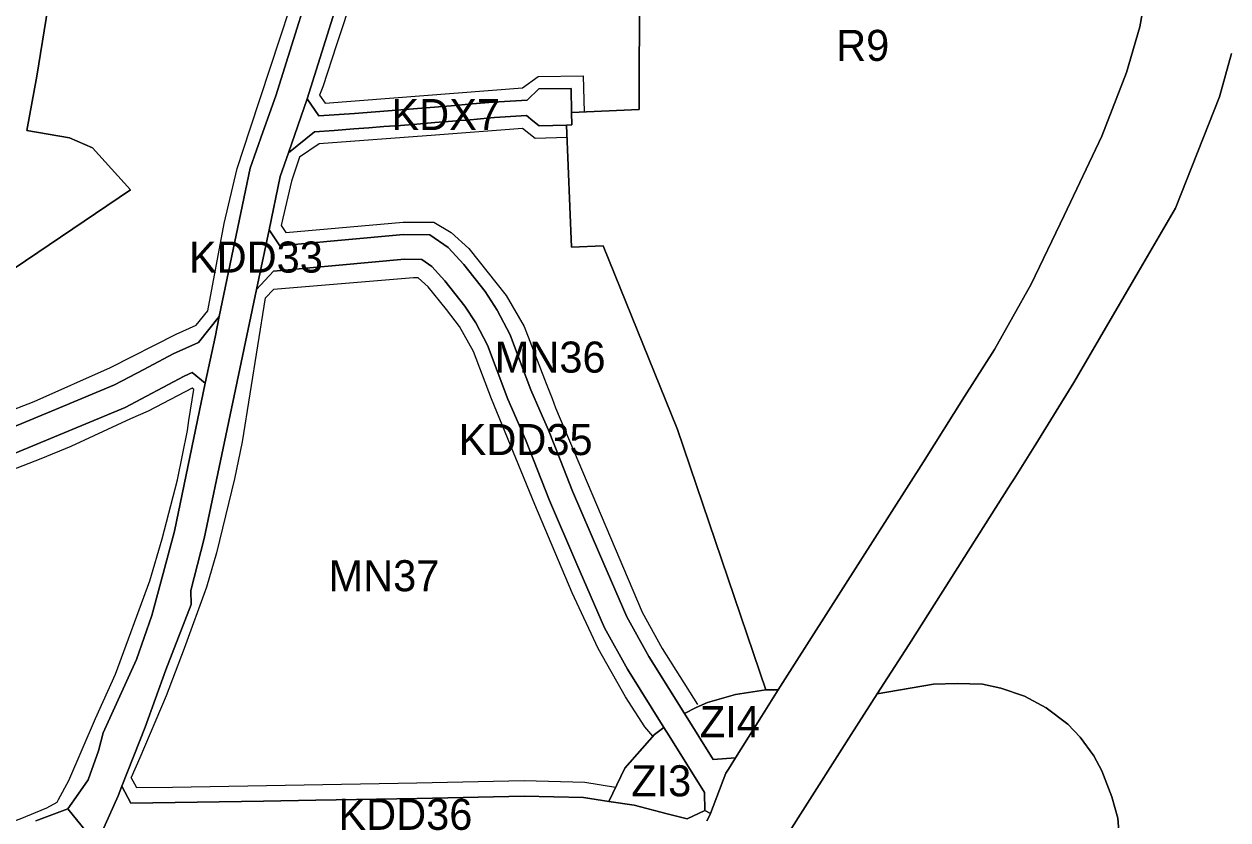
# Model space of a CAD drawing. Extents: x 7428841 to 7433518, y 5545054 to 5546840.
# Drawn here: x 7431568.9 to 7431956.4, y 5546005.4 to 5546261.6 of the extents above; entities that cross this region are included whole.
import ezdxf

# ---------------------------------------------------------------- set-up
doc = ezdxf.new("R2010")
doc.units = 0
for name, color, linetype in [('linie_rozgraniczajace', 7, 'Continuous'), ('linie_zabudowy_nieprzekraczalne', 7, 'Continuous'), ('oznaczenia_przeznaczen', 7, 'Continuous')]:
    doc.layers.add(name, color=color, linetype=linetype)

msp = doc.modelspace()

# ---------------------------------------------------------------- linework, layer by layer
at = {"layer": 'linie_rozgraniczajace'}
for points in [[(7431546.61, 5546302.36), (7431581.61, 5546322.94), (7431625.25, 5546344.76), (7431645.08, 5546352.52), (7431648.04, 5546353.82), (7431649.59, 5546329.66), (7431629.92, 5546324.21), (7431628.71, 5546297.68), (7431577.2, 5546270.87), (7431573.01, 5546244.86), (7431569.77, 5546227.41), (7431583.51, 5546224.99), (7431590.89, 5546221.81), (7431603.1, 5546208.27), (7431498.28, 5546137.46)], [(7431498.28, 5546137.46), (7431603.1, 5546208.27), (7431590.89, 5546221.81), (7431583.51, 5546224.99), (7431569.77, 5546227.41), (7431573.01, 5546244.86), (7431577.2, 5546270.87), (7431628.71, 5546297.68), (7431648.22, 5546299.54), (7431648.57, 5546306.31), (7431670.95, 5546315.15), (7431674.31, 5546316.64), (7431665.23, 5546287.62), (7431649.87, 5546238.51), (7431645.77, 5546226.85), (7431641.66, 5546215.2), (7431631.7, 5546167.48), (7431625.03, 5546159.14), (7431616.9, 5546155.4), (7431607.47, 5546150.42), (7431598.03, 5546145.44), (7431580.23, 5546138.04), (7431562.44, 5546130.63)], [(7431674.71, 5546284.42), (7431660.04, 5546237.52), (7431654.01, 5546220.15), (7431651.31, 5546212.5), (7431647.72, 5546195.4), (7431643.68, 5546176.2), (7431633.35, 5546127.08), (7431626.81, 5546095.96), (7431622.56, 5546079.22), (7431622.65, 5546074.73), (7431614.52, 5546053.71), (7431611.2, 5546044.48), (7431607.88, 5546035.26), (7431600.36, 5546016.23), (7431599.12, 5546013.1), (7431592.16, 5545997.56), (7431583, 5546008.93), (7431586.25, 5546013.62), (7431589.49, 5546018.31), (7431592.79, 5546027.59), (7431594.34, 5546033.44), (7431599.71, 5546045.24), (7431605.09, 5546057.05), (7431610.01, 5546071.18), (7431613.63, 5546084.76), (7431617.26, 5546098.34), (7431627.21, 5546146.01), (7431630.34, 5546160.78), (7431631.7, 5546167.48), (7431641.66, 5546215.2), (7431645.77, 5546226.85), (7431649.87, 5546238.51), (7431665.23, 5546287.62)], [(7431930.86, 5546276.41), (7431927.98, 5546260.72), (7431923.73, 5546245.99), (7431915.83, 5546225.51), (7431903.7, 5546199.96), (7431893.06, 5546177.91), (7431881.23, 5546156.88), (7431871.62, 5546141.76), (7431858.41, 5546120.71), (7431816.89, 5546055.56), (7431811.64, 5546047.22), (7431807.66, 5546047.21), (7431779.21, 5546131.09), (7431755.31, 5546190.25), (7431745.11, 5546189.84), (7431743.51, 5546229.12), (7431745.21, 5546229.17), (7431745.12, 5546233.11), (7431766.85, 5546234.13), (7431766.93, 5546274.9)], [(7431788.64, 5546005.06), (7431789.53, 5546006.64), (7431789.84, 5546007.46), (7431794.74, 5546020.38), (7431795.6, 5546021.73), (7431797.85, 5546025.31), (7431806.24, 5546038.64), (7431811.64, 5546047.22), (7431816.89, 5546055.56), (7431858.41, 5546120.71), (7431871.62, 5546141.76), (7431881.23, 5546156.88), (7431893.06, 5546177.91), (7431903.7, 5546199.96), (7431915.83, 5546225.51), (7431923.73, 5546245.99), (7431927.98, 5546260.72), (7431930.86, 5546276.41)], [(7431957.51, 5546252.19), (7431953.65, 5546238.16), (7431939.54, 5546202.36), (7431927.53, 5546181.78), (7431915.06, 5546160.4), (7431906.77, 5546146.18), (7431894.59, 5546126.38), (7431887.56, 5546115.23), (7431886.51, 5546113.57), (7431853.68, 5546061.76), (7431843.52, 5546046.02), (7431835.06, 5546032.92), (7431818, 5546006.01), (7431813.6, 5545999.06)], [(7431921.47, 5545998.98), (7431920.92, 5546005.95), (7431919.06, 5546012.76), (7431915.83, 5546021.16), (7431913.16, 5546026), (7431908.86, 5546032.02), (7431904.8, 5546036.2), (7431897.88, 5546041.48), (7431890.85, 5546045.25), (7431883.31, 5546047.84), (7431877.35, 5546049.04), (7431869.18, 5546049.29), (7431861.6, 5546049.13), (7431843.52, 5546046.02), (7431853.68, 5546061.76), (7431886.51, 5546113.57), (7431887.56, 5546115.23), (7431894.59, 5546126.38), (7431906.77, 5546146.18), (7431915.06, 5546160.4), (7431927.53, 5546181.78), (7431939.54, 5546202.36), (7431953.65, 5546238.16), (7431957.51, 5546252.19)], [(7431562.44, 5546130.63), (7431580.23, 5546138.04), (7431598.03, 5546145.44), (7431607.47, 5546150.42), (7431616.9, 5546155.4), (7431625.03, 5546159.14), (7431631.7, 5546167.48), (7431630.34, 5546160.78), (7431627.21, 5546146.01), (7431623.03, 5546149.42), (7431620.44, 5546148.22), (7431601.44, 5546138.2), (7431565.99, 5546123.45)], [(7431565.99, 5546123.45), (7431601.44, 5546138.2), (7431620.44, 5546148.22), (7431623.03, 5546149.42), (7431627.21, 5546146.01), (7431617.26, 5546098.34), (7431613.63, 5546084.76), (7431610.01, 5546071.18), (7431605.09, 5546057.05), (7431599.71, 5546045.24), (7431594.34, 5546033.44), (7431592.79, 5546027.59), (7431589.49, 5546018.31), (7431586.25, 5546013.62), (7431583, 5546008.93), (7431572.65, 5546005.07)], [(7431813.6, 5545999.06), (7431818, 5546006.01), (7431835.06, 5546032.92), (7431843.52, 5546046.02), (7431861.6, 5546049.13), (7431869.18, 5546049.29), (7431877.35, 5546049.04), (7431883.31, 5546047.84), (7431890.85, 5546045.25), (7431897.88, 5546041.48), (7431904.8, 5546036.2), (7431908.86, 5546032.02), (7431913.16, 5546026), (7431915.83, 5546021.16), (7431919.06, 5546012.76), (7431920.92, 5546005.95), (7431921.47, 5545998.98)], [(7431592.16, 5545997.56), (7431599.12, 5546013.1), (7431600.36, 5546016.23), (7431603.2, 5546010.76), (7431645.89, 5546011.46), (7431662.83, 5546011.75), (7431695.43, 5546012.29), (7431729.82, 5546013.04), (7431748.98, 5546012.55), (7431757.13, 5546011.34), (7431765.29, 5546010.13), (7431775.92, 5546007.36), (7431782.29, 5546005.69), (7431787.98, 5546008.39), (7431789.84, 5546007.46), (7431789.53, 5546006.64), (7431788.64, 5546005.06)], [(7431572.65, 5546005.07), (7431583, 5546008.93), (7431592.16, 5545997.56)]]:
    msp.add_lwpolyline(points, dxfattribs=at)
for points in [[(7431660.04, 5546237.52), (7431674.71, 5546284.42), (7431686.02, 5546320.6), (7431694.98, 5546323.51), (7431715.52, 5546327.92), (7431718.05, 5546333.49), (7431744.61, 5546337.67), (7431775.08, 5546333.48), (7431769.53, 5546274.71), (7431766.93, 5546274.9), (7431766.85, 5546234.13), (7431745.12, 5546233.11), (7431744.94, 5546240.93), (7431734.58, 5546240.75), (7431730.78, 5546237.16), (7431725.33, 5546236.85), (7431719.88, 5546236.53), (7431713.11, 5546235.93), (7431706.33, 5546235.33), (7431675.2, 5546232.86), (7431663.77, 5546232.04)], [(7431654.01, 5546220.15), (7431660.04, 5546237.52), (7431663.77, 5546232.04), (7431675.2, 5546232.86), (7431706.33, 5546235.33), (7431713.11, 5546235.93), (7431719.88, 5546236.53), (7431725.33, 5546236.85), (7431730.78, 5546237.16), (7431734.58, 5546240.75), (7431744.94, 5546240.93), (7431745.12, 5546233.11), (7431745.21, 5546229.17), (7431743.51, 5546229.12), (7431734.7, 5546228.87), (7431732.62, 5546230.5), (7431730.55, 5546232.14), (7431720.25, 5546231.54), (7431715.84, 5546231.14), (7431711.44, 5546230.73), (7431709.1, 5546230.54), (7431706.75, 5546230.34), (7431701.04, 5546229.89), (7431695.34, 5546229.44), (7431690.02, 5546229.02), (7431684.71, 5546228.6), (7431679.89, 5546228.24), (7431675.07, 5546227.89), (7431668.71, 5546227.41), (7431662.35, 5546226.92)], [(7431647.72, 5546195.4), (7431651.31, 5546212.5), (7431654.01, 5546220.15), (7431662.35, 5546226.92), (7431668.71, 5546227.41), (7431675.07, 5546227.89), (7431679.89, 5546228.24), (7431684.71, 5546228.6), (7431690.02, 5546229.02), (7431695.34, 5546229.44), (7431701.04, 5546229.89), (7431706.75, 5546230.34), (7431709.1, 5546230.54), (7431711.44, 5546230.73), (7431715.84, 5546231.14), (7431720.25, 5546231.54), (7431730.55, 5546232.14), (7431732.62, 5546230.5), (7431734.7, 5546228.87), (7431743.51, 5546229.12), (7431745.11, 5546189.84), (7431755.31, 5546190.25), (7431779.21, 5546131.09), (7431807.66, 5546047.21), (7431797.83, 5546045.71), (7431788.87, 5546043.18), (7431785.16, 5546041.61), (7431781.45, 5546039.64), (7431769.99, 5546057.98), (7431762.88, 5546070.76), (7431754.14, 5546091.01), (7431745.39, 5546111.26), (7431741.52, 5546121.08), (7431737.64, 5546130.9), (7431734.91, 5546137.19), (7431732.02, 5546143.87), (7431728.69, 5546152.7), (7431725.36, 5546161.53), (7431721.19, 5546169.47), (7431717.25, 5546175.52), (7431710.42, 5546184.19), (7431705.37, 5546189.65), (7431699.43, 5546193.82), (7431691.04, 5546193.88), (7431671.09, 5546192.07), (7431651.15, 5546190.27)], [(7431643.68, 5546176.2), (7431647.72, 5546195.4), (7431651.15, 5546190.27), (7431671.09, 5546192.07), (7431691.04, 5546193.88), (7431699.43, 5546193.82), (7431705.37, 5546189.65), (7431710.42, 5546184.19), (7431717.25, 5546175.52), (7431721.19, 5546169.47), (7431725.36, 5546161.53), (7431728.69, 5546152.7), (7431732.02, 5546143.87), (7431734.91, 5546137.19), (7431737.64, 5546130.9), (7431741.52, 5546121.08), (7431745.39, 5546111.26), (7431754.14, 5546091.01), (7431762.88, 5546070.76), (7431769.99, 5546057.98), (7431781.45, 5546039.64), (7431790.69, 5546024.83), (7431797.85, 5546025.31), (7431795.6, 5546021.73), (7431794.74, 5546020.38), (7431789.84, 5546007.46), (7431787.98, 5546008.39), (7431787.92, 5546014.17), (7431776.5, 5546032.46), (7431774.81, 5546035.17), (7431763.1, 5546053.92), (7431755.7, 5546067.22), (7431746.85, 5546087.72), (7431737.99, 5546108.21), (7431730.25, 5546127.84), (7431724.6, 5546140.87), (7431718.05, 5546158.24), (7431714.28, 5546165.42), (7431710.74, 5546170.85), (7431704.33, 5546178.99), (7431700.08, 5546183.59), (7431696.88, 5546185.84), (7431691.37, 5546185.88), (7431670.28, 5546183.97), (7431649.19, 5546182.06)], [(7431600.36, 5546016.23), (7431607.88, 5546035.26), (7431611.2, 5546044.48), (7431614.52, 5546053.71), (7431622.65, 5546074.73), (7431622.56, 5546079.22), (7431626.81, 5546095.96), (7431633.35, 5546127.08), (7431643.68, 5546176.2), (7431649.19, 5546182.06), (7431670.28, 5546183.97), (7431691.37, 5546185.88), (7431696.88, 5546185.84), (7431700.08, 5546183.59), (7431704.33, 5546178.99), (7431710.74, 5546170.85), (7431714.28, 5546165.42), (7431718.05, 5546158.24), (7431724.6, 5546140.87), (7431730.25, 5546127.84), (7431737.99, 5546108.21), (7431746.85, 5546087.72), (7431755.7, 5546067.22), (7431763.1, 5546053.92), (7431774.81, 5546035.17), (7431771.81, 5546032.83), (7431762.2, 5546022.04), (7431757.13, 5546011.34), (7431748.98, 5546012.55), (7431729.82, 5546013.04), (7431695.43, 5546012.29), (7431662.83, 5546011.75), (7431645.89, 5546011.46), (7431603.2, 5546010.76)], [(7431781.45, 5546039.64), (7431785.16, 5546041.61), (7431788.87, 5546043.18), (7431797.83, 5546045.71), (7431807.66, 5546047.21), (7431811.64, 5546047.22), (7431806.24, 5546038.64), (7431797.85, 5546025.31), (7431790.69, 5546024.83)], [(7431757.13, 5546011.34), (7431762.2, 5546022.04), (7431771.81, 5546032.83), (7431774.81, 5546035.17), (7431776.5, 5546032.46), (7431787.92, 5546014.17), (7431787.98, 5546008.39), (7431782.29, 5546005.69), (7431775.92, 5546007.36), (7431765.29, 5546010.13)]]:
    msp.add_lwpolyline(points, close=True, dxfattribs=at)
at = {"layer": 'linie_zabudowy_nieprzekraczalne'}
for points in [[(7431706.62, 5546365.53), (7431692.58, 5546324.35), (7431680.29, 5546287.84), (7431669.44, 5546255), (7431665.05, 5546241.43), (7431664, 5546238.76)], [(7431628.05, 5546169.3), (7431633.33, 5546197.4), (7431637.47, 5546215.13), (7431641.6, 5546227.85), (7431664.06, 5546296.07), (7431667.14, 5546305.63), (7431673.68, 5546324.85), (7431683.59, 5546353.3), (7431685.3, 5546359.17), (7431684.87, 5546362.45)], [(7431664, 5546238.76), (7431664, 5546238.76), (7431665.76, 5546236.2), (7431729.33, 5546241.06), (7431734.38, 5546244.78), (7431748.85, 5546244.98), (7431749.11, 5546233.32)], [(7431743.68, 5546225.13), (7431733.36, 5546224.83), (7431729.3, 5546228.04), (7431701.35, 5546225.9), (7431663.91, 5546223.03), (7431657.5, 5546218.74)], [(7431657.5, 5546218.74), (7431654.99, 5546211.02), (7431652.21, 5546199.11), (7431651.6, 5546196.78)], [(7431651.6, 5546196.78), (7431653.15, 5546194.47), (7431690.87, 5546197.88), (7431700.73, 5546197.81), (7431706.33, 5546194.56), (7431712.01, 5546189.39), (7431724, 5546174.27), (7431729.86, 5546164.29), (7431736.96, 5546145.95), (7431738.81, 5546141.11), (7431739.93, 5546138.1)], [(7431771.25, 5546032.29), (7431768.71, 5546035.32), (7431762.46, 5546045.05), (7431753.68, 5546060.52), (7431745.25, 5546078.54), (7431733.24, 5546106.92), (7431719.38, 5546141.01), (7431713.56, 5546156.16), (7431709.03, 5546164.21), (7431704.82, 5546169.74), (7431698.91, 5546176.97), (7431695.72, 5546179.88), (7431694.25, 5546179.94), (7431649.11, 5546176.14), (7431646.6, 5546173.46)], [(7431646.53, 5546173.48), (7431639.11, 5546127.08), (7431636.64, 5546115.24), (7431630.79, 5546091.4), (7431627.62, 5546080.36), (7431620.37, 5546060.55), (7431614.66, 5546045.33), (7431606.16, 5546025.41), (7431603.36, 5546019.03)], [(7431556.27, 5546133.97), (7431572.08, 5546140.12), (7431596.73, 5546151.06), (7431617.88, 5546161.83), (7431624.31, 5546164.63), (7431628.05, 5546169.3)], [(7431623.49, 5546143.95), (7431623.01, 5546144.37), (7431608.79, 5546136.94), (7431603.14, 5546134.57), (7431583.88, 5546125.63), (7431574.29, 5546121.64), (7431564.58, 5546117.89)], [(7431579.49, 5546011.06), (7431579.95, 5546011.9), (7431583.33, 5546018.11), (7431591.9, 5546038), (7431598.27, 5546052.27), (7431609.32, 5546082.36), (7431613.35, 5546095.87), (7431618.21, 5546114.83), (7431621.49, 5546130.72), (7431621.9, 5546134), (7431623.49, 5546143.95)], [(7431739.93, 5546138.1), (7431767.82, 5546072.31), (7431774.3, 5546060.53), (7431785.62, 5546042.57)], [(7431603.28, 5546019.14), (7431605.02, 5546015.76), (7431616.6, 5546015.92), (7431695.34, 5546017.26), (7431729.84, 5546018.04), (7431749.41, 5546017.54), (7431759.29, 5546015.96)], [(7431179.86, 5545828.51), (7431194.55, 5545832.95), (7431208.56, 5545838.51), (7431222.38, 5545847.36), (7431241, 5545860.79), (7431254.18, 5545867.16), (7431290.1, 5545877.07), (7431303.51, 5545880.27), (7431315.58, 5545884.55), (7431328.71, 5545890.98), (7431356.1, 5545909.93), (7431377.12, 5545923.45), (7431455.24, 5545969.15), (7431477.61, 5545979.11), (7431507.9, 5545987.31), (7431541.37, 5545997.7), (7431556.39, 5546001.76), (7431567.62, 5546005.71), (7431576.19, 5546009.27), (7431579.49, 5546011.06)]]:
    msp.add_lwpolyline(points, dxfattribs=at)

# ---------------------------------------------------------------- texts
at = {"layer": 'oznaczenia_przeznaczen'}
for s, p in [('R9', (7431830.27, 5546249.77)), ('KDX7', (7431687.13, 5546227.51)), ('KDD33', (7431621.94, 5546181.61)), ('MN36', (7431720.38, 5546149.4)), ('KDD35', (7431708.77, 5546122.84)), ('MN37', (7431666.88, 5546079)), ('ZI4', (7431786.39, 5546032)), ('ZI3', (7431764.3, 5546012.97)), ('KDD36', (7431670.07, 5546002.17))]:
    msp.add_text(s, height=10, dxfattribs=at).set_placement(p)

doc.saveas('drawing.dxf')
